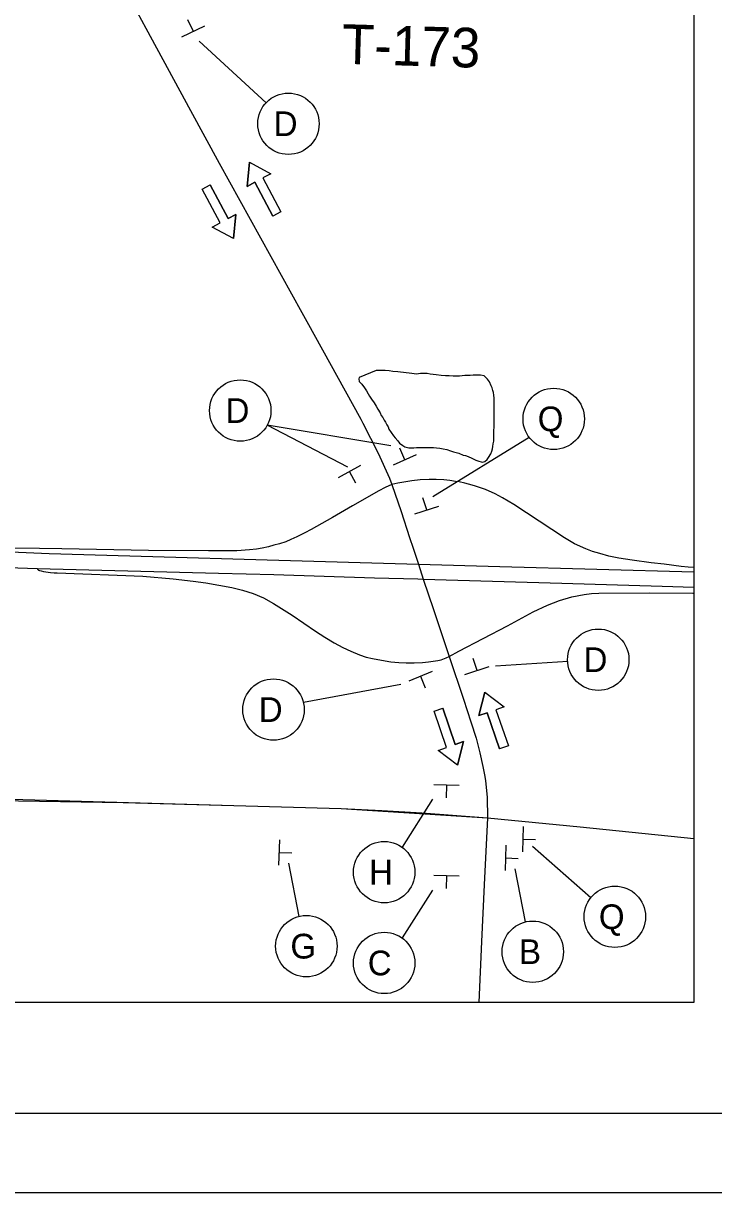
# Model space of a CAD drawing. Extents: x 1 to 1971, y -2 to 1107.
# Drawn here: x 1667.97 to 1672.33, y 1084.6 to 1091.98 of the extents above; entities that cross this region are included whole.
import ezdxf

# ---------------------------------------------------------------- set-up
doc = ezdxf.new("R2010")
doc.units = 0
for name, color, linetype in [('GM_X_County_Road', 7, 'Continuous'), ('GM_X_Interchange_Ramps', 7, 'Continuous'), ('GM_X_Minor_River', 7, 'Continuous'), ('GM_X_State_Route', 7, 'Continuous'), ('GM_X_Township_Road_Text', 7, 'Continuous'), ('SH_Border', 7, 'Continuous'), ('SH_Cut_Line', 7, 'Continuous'), ('SH_Data', 7, 'Continuous'), ('SH_Text', 7, 'Continuous'), ('SN_P_Signs', 7, 'Continuous')]:
    doc.layers.add(name, color=color, linetype=linetype)

msp = doc.modelspace()

# ---------------------------------------------------------------- linework, layer by layer
at = {"layer": 'GM_X_County_Road'}
for points in [[(1663.7236, 1087.1696), (1664.183, 1087.1576), (1665.0579, 1087.1385), (1665.5171, 1087.1234), (1666.4577, 1087.0978), (1666.9606, 1087.0776), (1667.1575, 1087.0752), (1667.5292, 1087.089), (1667.748, 1087.0865), (1669.3011, 1087.0422), (1669.9792, 1087.0232), (1670.236, 1087.0104), (1670.4866, 1086.997), (1670.9021, 1086.9648)], [(1670.9021, 1086.9648), (1671.4857, 1086.9077), (1672.2022, 1086.8351)]]:
    msp.add_lwpolyline(points, dxfattribs=at)
at = {"layer": 'GM_X_Interchange_Ramps'}
for points in [[(1672.2022, 1088.5443), (1672.1673, 1088.5472), (1672.1239, 1088.5515), (1672.0153, 1088.5646), (1671.933, 1088.5745), (1671.8143, 1088.5912), (1671.7292, 1088.6027), (1671.6671, 1088.616), (1671.6105, 1088.6317), (1671.5648, 1088.6458), (1671.5222, 1088.6617), (1671.4496, 1088.693), (1671.3867, 1088.7314), (1671.0669, 1088.9414), (1670.9953, 1088.9838), (1670.9505, 1089.0098), (1670.8883, 1089.0361), (1670.8187, 1089.06), (1670.7829, 1089.0703), (1670.7585, 1089.0765), (1670.7232, 1089.0839), (1670.7009, 1089.0878), (1670.6645, 1089.0938), (1670.6272, 1089.0969), (1670.5784, 1089.0993), (1670.5335, 1089.0997), (1670.4762, 1089.0969), (1670.4239, 1089.0917), (1670.3741, 1089.0837), (1670.3362, 1089.0757), (1670.2981, 1089.0677)], [(1670.2981, 1089.0677), (1670.2568, 1089.0488), (1670.2167, 1089.0283), (1670.0508, 1088.9331), (1669.9238, 1088.8603), (1669.7897, 1088.7843), (1669.7496, 1088.7631), (1669.6993, 1088.7371), (1669.6616, 1088.7206), (1669.6293, 1088.7072), (1669.5892, 1088.6938), (1669.5546, 1088.6843), (1669.52, 1088.6749), (1669.4814, 1088.6668), (1669.4445, 1088.6599), (1669.3997, 1088.6548), (1669.3218, 1088.6496), (1669.1426, 1088.6487), (1668.7639, 1088.6514), (1668.2163, 1088.6613), (1668.0763, 1088.6637), (1667.6527, 1088.6689)], [(1668.0608, 1088.5378), (1668.0658, 1088.5323), (1668.071, 1088.5285), (1668.0765, 1088.5255), (1668.0863, 1088.5225), (1668.1025, 1088.5195), (1668.1317, 1088.5151), (1668.1456, 1088.5135), (1668.1682, 1088.5112), (1668.1867, 1088.5102), (1668.7281, 1088.4896), (1668.9194, 1088.4732), (1669.0461, 1088.4591), (1669.1255, 1088.4474), (1669.2065, 1088.4335), (1669.2897, 1088.4174), (1669.3562, 1088.4008), (1669.4228, 1088.3794), (1669.4888, 1088.352), (1669.5516, 1088.3182), (1669.6696, 1088.2437), (1669.8168, 1088.1433), (1669.8755, 1088.1044), (1669.9352, 1088.0692), (1669.9899, 1088.0391), (1670.0397, 1088.0173), (1670.0946, 1087.9937), (1670.1374, 1087.9794), (1670.1773, 1087.9692), (1670.2111, 1087.9636), (1670.2928, 1087.9497), (1670.3433, 1087.9458), (1670.3887, 1087.9438), (1670.4383, 1087.9428), (1670.4909, 1087.9454), (1670.5292, 1087.9484), (1670.5598, 1087.9525), (1670.5879, 1087.9577), (1670.6088, 1087.9623), (1670.6418, 1087.9741), (1670.6608, 1087.9827)], [(1670.6608, 1087.9827), (1670.7211, 1088.0173), (1671.0282, 1088.1772), (1671.1896, 1088.2649), (1671.2792, 1088.3068), (1671.355, 1088.3368), (1671.4327, 1088.3587), (1671.5104, 1088.3747), (1671.5577, 1088.3807), (1671.6041, 1088.3827), (1671.921, 1088.3848), (1672.196, 1088.3822), (1672.2022, 1088.3821)]]:
    msp.add_lwpolyline(points, dxfattribs=at)
at = {"layer": 'GM_X_Minor_River'}
for points in [[(1670.2106, 1089.5438), (1670.2239, 1089.5197), (1670.2319, 1089.5036), (1670.2425, 1089.4902), (1670.2505, 1089.4741), (1670.2585, 1089.4607), (1670.2665, 1089.4446), (1670.2745, 1089.4312), (1670.2798, 1089.4179), (1670.3092, 1089.3749), (1670.3199, 1089.3615), (1670.3359, 1089.3427), (1670.3465, 1089.3293), (1670.3679, 1089.3132), (1670.3813, 1089.3051), (1670.4053, 1089.2997), (1670.4187, 1089.2997), (1670.4375, 1089.2996), (1670.4535, 1089.3022), (1670.4722, 1089.3022), (1670.499, 1089.3021), (1670.5177, 1089.302), (1670.5391, 1089.302), (1670.5605, 1089.3019), (1670.5793, 1089.2991), (1670.6007, 1089.2964), (1670.6221, 1089.2937), (1670.6461, 1089.2882), (1670.6675, 1089.2801), (1670.6863, 1089.2747), (1670.705, 1089.2693), (1670.721, 1089.2666), (1670.7477, 1089.2531), (1670.7638, 1089.2504), (1670.7798, 1089.245), (1670.8039, 1089.2342), (1670.8279, 1089.2208), (1670.8413, 1089.2181), (1670.8681, 1089.2099), (1670.8841, 1089.2126), (1670.9002, 1089.2259), (1670.9083, 1089.2392), (1670.9217, 1089.2606), (1670.9298, 1089.2793), (1670.9325, 1089.2927), (1670.9352, 1089.3087), (1670.9379, 1089.3247), (1670.9406, 1089.3408), (1670.9408, 1089.4077), (1670.9435, 1089.4291), (1670.9435, 1089.4478), (1670.9436, 1089.4665), (1670.9436, 1089.4853), (1670.9437, 1089.4986), (1670.9437, 1089.52), (1670.9438, 1089.5441), (1670.9438, 1089.5736), (1670.9439, 1089.5923), (1670.9439, 1089.6137), (1670.9413, 1089.6324), (1670.9387, 1089.6485), (1670.936, 1089.6619), (1670.9307, 1089.6779), (1670.9254, 1089.6913), (1670.9147, 1089.7155), (1670.9014, 1089.7315), (1670.88, 1089.753), (1670.8586, 1089.7584), (1670.8399, 1089.7585), (1670.8238, 1089.7585), (1670.8105, 1089.7586), (1670.7917, 1089.756), (1670.7757, 1089.756), (1670.7596, 1089.7561), (1670.7409, 1089.7535), (1670.7248, 1089.7508), (1670.7061, 1089.7509), (1670.6847, 1089.751), (1670.6606, 1089.7537), (1670.6365, 1089.7538), (1670.6098, 1089.7566), (1670.5777, 1089.7593), (1670.5589, 1089.7621), (1670.5402, 1089.7648), (1670.5215, 1089.7675), (1670.5027, 1089.7676), (1670.4787, 1089.7677), (1670.4546, 1089.7651), (1670.4251, 1089.7679), (1670.3369, 1089.7789), (1670.3048, 1089.7816), (1670.2807, 1089.7844), (1670.2566, 1089.7871), (1670.2352, 1089.7872), (1670.2165, 1089.7873), (1670.2004, 1089.7873), (1670.0933, 1089.7422)], [(1670.0933, 1089.7422), (1670.0906, 1089.7342), (1670.0932, 1089.7181), (1670.1093, 1089.702), (1670.1252, 1089.6779), (1670.1386, 1089.6591), (1670.1492, 1089.6403), (1670.1572, 1089.6243), (1670.1706, 1089.6055), (1670.1866, 1089.584), (1670.1999, 1089.5626), (1670.2106, 1089.5438)]]:
    msp.add_lwpolyline(points, dxfattribs=at)
at = {"layer": 'GM_X_State_Route'}
msp.add_line((1670.9021, 1086.9648), (1670.8815, 1086.5425), dxfattribs=at)
for points in [[(1653.1763, 1088.972), (1654.1058, 1088.9448), (1655.1549, 1088.9137), (1655.8542, 1088.8935), (1656.6489, 1088.8688), (1657.2445, 1088.8506), (1657.6825, 1088.8393), (1658.51, 1088.8187), (1659.3192, 1088.7948), (1660.9157, 1088.748), (1661.55, 1088.7295), (1662.0093, 1088.7178), (1663.1466, 1088.6833), (1663.7686, 1088.6652), (1664.4369, 1088.6454), (1665.8366, 1088.6041), (1666.8645, 1088.5732), (1667.7577, 1088.5488), (1668.0608, 1088.5378), (1669.2047, 1088.5077), (1669.5547, 1088.5002), (1670.1889, 1088.4798), (1670.4622, 1088.472)], [(1659.6102, 1088.8844), (1660.288, 1088.8659), (1660.8126, 1088.8494), (1661.4466, 1088.8312), (1662.4959, 1088.8007), (1663.3048, 1088.777), (1663.7714, 1088.7638), (1663.8294, 1088.7624), (1664.6819, 1088.737), (1665.1629, 1088.7239), (1665.8187, 1088.7038), (1666.2558, 1088.6901), (1667.4561, 1088.6514), (1667.5998, 1088.6492), (1667.8954, 1088.6435), (1668.1374, 1088.6337), (1668.7912, 1088.6143), (1669.5117, 1088.5931), (1670.4659, 1088.5658), (1670.98, 1088.5507), (1672.2022, 1088.5164)], [(1670.4622, 1088.472), (1670.4969, 1088.471), (1671.3698, 1088.4461), (1672.0041, 1088.4259), (1672.2022, 1088.4198)], [(1670.8815, 1086.5425), (1670.864, 1086.1852), (1670.8468, 1085.8005)]]:
    msp.add_lwpolyline(points, dxfattribs=at)
at = {"layer": 'SH_Border'}
msp.add_lwpolyline([(1652.9632, 1106.1005), (1684.9632, 1106.1005), (1684.9632, 1085.1005), (1652.9632, 1085.1005)], close=True, dxfattribs=at)
at = {"layer": 'SH_Cut_Line'}
msp.add_lwpolyline([(1651.4632, 1084.6005), (1685.4632, 1084.6005), (1685.4632, 1106.6005), (1651.4632, 1106.6005)], close=True, dxfattribs=at)
at = {"layer": 'SH_Data'}
msp.add_lwpolyline([(1653.1763, 1105.4005), (1672.2022, 1105.4005), (1672.2022, 1085.8005), (1653.1763, 1085.8005)], close=True, dxfattribs=at)
at = {"layer": 'SH_Text'}
for p, q in [((1669.0841, 1091.8651), (1669.5054, 1091.4769)), ((1669.4001, 1091.1012), (1669.3853, 1090.9488)), ((1669.4001, 1091.1012), (1669.5349, 1091.0287)), ((1669.5349, 1091.0287), (1669.4847, 1091.0018)), ((1669.4847, 1091.0018), (1669.5986, 1090.7883)), ((1669.1016, 1090.9321), (1669.1528, 1090.9595)), ((1669.2156, 1090.7186), (1669.1016, 1090.9321)), ((1669.2668, 1090.7459), (1669.1528, 1090.9595)), ((1669.3853, 1090.9488), (1669.4335, 1090.9745)), ((1669.4335, 1090.9745), (1669.5475, 1090.761)), ((1669.5986, 1090.7883), (1669.5475, 1090.761)), ((1669.1653, 1090.6918), (1669.2156, 1090.7186)), ((1669.3149, 1090.7716), (1669.2668, 1090.7459)), ((1669.3001, 1090.6192), (1669.3149, 1090.7716)), ((1669.3001, 1090.6192), (1669.1653, 1090.6918)), ((1670.0205, 1089.1769), (1669.513, 1089.4427)), ((1670.2927, 1089.3114), (1669.513, 1089.4427)), ((1670.5568, 1088.993), (1671.1645, 1089.3656)), ((1670.9518, 1087.9243), (1671.4088, 1087.9544)), ((1670.3554, 1087.8065), (1669.7406, 1087.6919)), ((1670.8859, 1087.7586), (1670.8475, 1087.6104)), ((1670.8859, 1087.7586), (1671.0078, 1087.666)), ((1670.5647, 1087.6381), (1670.6195, 1087.6571)), ((1670.644, 1087.4094), (1670.5647, 1087.6381)), ((1670.6988, 1087.4285), (1670.6195, 1087.6571)), ((1670.8475, 1087.6104), (1670.8991, 1087.6283)), ((1670.8991, 1087.6283), (1670.9784, 1087.3996)), ((1671.0078, 1087.666), (1670.9539, 1087.6473)), ((1670.9539, 1087.6473), (1671.0332, 1087.4186)), ((1670.5901, 1087.3908), (1670.644, 1087.4094)), ((1670.712, 1087.2981), (1670.5901, 1087.3908)), ((1670.7504, 1087.4464), (1670.6988, 1087.4285)), ((1670.712, 1087.2981), (1670.7504, 1087.4464)), ((1671.0332, 1087.4186), (1670.9784, 1087.3996)), ((1666.6353, 1087.0907), (1668.6047, 1087.0621)), ((1668.6047, 1087.0621), (1669.3011, 1087.0422)), ((1669.3011, 1087.0422), (1669.9792, 1087.0232)), ((1669.9792, 1087.0232), (1670.9021, 1086.9648)), ((1670.5556, 1087.0822), (1670.3625, 1086.7799)), ((1671.1855, 1086.7873), (1671.5543, 1086.4627)), ((1669.646, 1086.6784), (1669.7117, 1086.3431)), ((1671.0737, 1086.6434), (1671.1395, 1086.3081)), ((1670.5556, 1086.5094), (1670.3625, 1086.2071))]:
    msp.add_line(p, q, dxfattribs=at)
for points in [[(1667.0331, 1094.9821), (1667.036, 1094.9775), (1667.3422, 1094.472), (1667.5124, 1094.191), (1667.5577, 1094.1145), (1667.6338, 1093.9829), (1667.8558, 1093.5802), (1667.9723, 1093.3696), (1668.2781, 1092.8131), (1668.4867, 1092.4282), (1668.6651, 1092.0989), (1668.7474, 1091.947), (1669.0282, 1091.4269), (1669.2085, 1091.0948), (1669.731, 1090.1531)], [(1669.731, 1090.1531), (1669.7621, 1090.097), (1670.1018, 1089.4808)], [(1670.1018, 1089.4808), (1670.1157, 1089.4557), (1670.2126, 1089.265), (1670.2844, 1089.1076), (1670.2981, 1089.0677), (1670.3562, 1088.8983), (1670.4096, 1088.7343), (1670.4324, 1088.6659)], [(1670.4324, 1088.6659), (1670.4659, 1088.5658), (1670.4969, 1088.471), (1670.5604, 1088.2785), (1670.6608, 1087.9827), (1670.7502, 1087.7129), (1670.7973, 1087.5712), (1670.8312, 1087.4675), (1670.8531, 1087.3759), (1670.8731, 1087.2882), (1670.8824, 1087.2373)], [(1670.8824, 1087.2373), (1670.8891, 1087.2005), (1670.8991, 1087.0929), (1670.9021, 1086.9648)]]:
    msp.add_lwpolyline(points, dxfattribs=at)
for points in [[(1669.5475, 1090.761), (1669.4335, 1090.9745), (1669.3853, 1090.9488), (1669.4001, 1091.1012), (1669.5349, 1091.0287), (1669.4847, 1091.0018), (1669.5986, 1090.7883)], [(1669.1528, 1090.9595), (1669.2668, 1090.7459), (1669.3149, 1090.7716), (1669.3002, 1090.6192), (1669.1653, 1090.6918), (1669.2156, 1090.7186), (1669.1016, 1090.9321)], [(1670.9784, 1087.3996), (1670.8991, 1087.6283), (1670.8475, 1087.6104), (1670.8858, 1087.7586), (1671.0077, 1087.666), (1670.9539, 1087.6473), (1671.0332, 1087.4186)], [(1670.6195, 1087.6571), (1670.6988, 1087.4285), (1670.7504, 1087.4464), (1670.7121, 1087.2981), (1670.5902, 1087.3908), (1670.644, 1087.4095), (1670.5647, 1087.6381)]]:
    msp.add_lwpolyline(points, close=True, dxfattribs=at)
for centre in [(1669.6462, 1091.344), (1669.3425, 1089.5345), (1671.3193, 1089.4819), (1671.6003, 1087.9626), (1669.552, 1087.648), (1670.2502, 1086.6222), (1671.7048, 1086.3409), (1669.7593, 1086.1554), (1671.1871, 1086.1204), (1670.2502, 1086.0494)]:
    msp.add_circle(centre, 0.1936, dxfattribs=at)
at = {"layer": 'SN_P_Signs'}
for p, q in [((1668.9749, 1091.8917), (1669.119, 1091.9612)), ((1669.0469, 1091.9264), (1669.0122, 1091.9985)), ((1670.3084, 1089.1911), (1670.454, 1089.2574)), ((1670.3812, 1089.2242), (1670.3481, 1089.297)), ((1670.101, 1089.1869), (1669.9608, 1089.1099)), ((1670.0309, 1089.1484), (1670.0694, 1089.0783)), ((1670.5194, 1088.9074), (1670.4947, 1088.9834)), ((1670.4433, 1088.8826), (1670.5955, 1088.9321)), ((1670.7596, 1087.8694), (1670.9117, 1087.9188)), ((1670.8356, 1087.8941), (1670.8109, 1087.9702)), ((1670.5531, 1087.8886), (1670.4051, 1087.8278)), ((1670.4791, 1087.8582), (1670.5094, 1087.7842)), ((1670.7235, 1087.1692), (1670.5636, 1087.1734)), ((1670.6436, 1087.1713), (1670.6415, 1087.0913)), ((1671.1272, 1086.9097), (1671.1224, 1086.7498)), ((1669.5894, 1086.8268), (1669.5846, 1086.6669)), ((1671.1248, 1086.8297), (1671.2048, 1086.8273)), ((1669.587, 1086.7468), (1669.667, 1086.7444)), ((1671.0172, 1086.7918), (1671.0124, 1086.6318)), ((1671.0148, 1086.7118), (1671.0948, 1086.7094)), ((1670.7235, 1086.5963), (1670.5636, 1086.6005)), ((1670.6436, 1086.5984), (1670.6415, 1086.5184))]:
    msp.add_line(p, q, dxfattribs=at)

# ---------------------------------------------------------------- texts
at = {"layer": 'GM_X_Township_Road_Text'}
msp.add_text('T-173', height=0.25, rotation=358.31519, dxfattribs=at).set_placement((1669.98, 1091.7226))
at = {"layer": 'SH_Text'}
for s, p in [('D', (1669.5532, 1091.266)), ('D', (1669.2495, 1089.4565)), ('Q', (1671.2185, 1089.4039)), ('D', (1671.5073, 1087.8846)), ('D', (1669.459, 1087.57)), ('H', (1670.1546, 1086.5442)), ('Q', (1671.604, 1086.2629)), ('G', (1669.6587, 1086.0774)), ('C', (1670.1465, 1085.9714)), ('B', (1671.1002, 1086.0424))]:
    msp.add_text(s, height=0.156, dxfattribs=at).set_placement(p)

doc.saveas('drawing.dxf')
